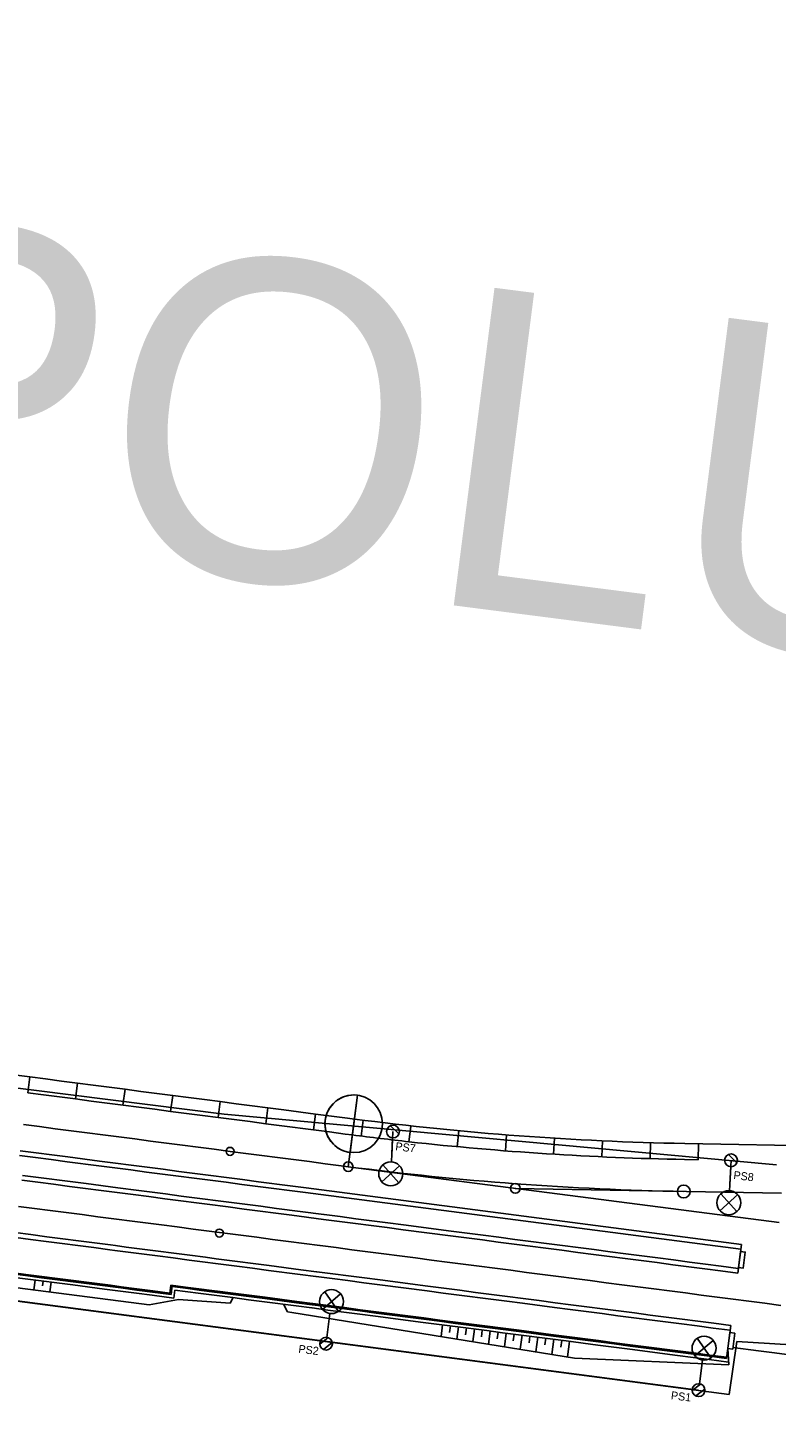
# Model space of a CAD drawing. Extents: x -669661 to -669105, y -977202 to -977030.
# Drawn here: x -669175.034 to -669172.695, y -977098.424 to -977094.133 of the extents above; entities that cross this region are included whole.
import ezdxf

# ---------------------------------------------------------------- set-up
doc = ezdxf.new("R2010")
doc.units = 0
doc.layers.add('Schéma', color=7, linetype='Continuous')

msp = doc.modelspace()

# ---------------------------------------------------------------- linework, layer by layer
at = {"layer": 'Schéma'}
for p, q in [((-669174.42, -977097.5262), (-669175.313, -977097.4136)), ((-669174.0323, -977097.6905), (-669174.0034, -977097.4674)), ((-669172.6955, -977097.6847), (-669174.42, -977097.5262)), ((-669175.0459, -977097.5589), (-669174.9963, -977097.5653)), ((-669174.9963, -977097.5653), (-669174.9468, -977097.5718)), ((-669174.9468, -977097.5718), (-669174.8972, -977097.5782)), ((-669174.8972, -977097.5782), (-669174.8476, -977097.5846)), ((-669174.8476, -977097.5846), (-669174.798, -977097.5911)), ((-669173.9008, -977097.5627), (-669173.8751, -977097.587)), ((-669173.8927, -977097.5807), (-669173.8966, -977097.6556)), ((-669173.6872, -977097.5783), (-669173.6919, -977097.628)), ((-669174.798, -977097.5911), (-669174.7484, -977097.5975)), ((-669174.7484, -977097.5975), (-669174.6988, -977097.6039)), ((-669174.6988, -977097.6039), (-669174.6493, -977097.6104)), ((-669174.6493, -977097.6104), (-669174.5997, -977097.6168)), ((-669174.5997, -977097.6168), (-669174.5501, -977097.6233)), ((-669174.5501, -977097.6233), (-669174.5005, -977097.6297)), ((-669174.5005, -977097.6297), (-669174.4509, -977097.6361)), ((-669173.8937, -977097.6006), (-669173.8976, -977097.6755)), ((-669173.5377, -977097.5911), (-669173.5416, -977097.641)), ((-669173.3881, -977097.6016), (-669173.3912, -977097.6515)), ((-669173.2383, -977097.6097), (-669173.2406, -977097.6597)), ((-669173.0884, -977097.6154), (-669173.0899, -977097.6654)), ((-669172.9385, -977097.6188), (-669172.9394, -977097.6688)), ((-669174.4509, -977097.6361), (-669174.4013, -977097.6426)), ((-669174.4013, -977097.6426), (-669174.3518, -977097.649)), ((-669174.3518, -977097.649), (-669174.3022, -977097.6555)), ((-669174.3022, -977097.6555), (-669174.2526, -977097.6619)), ((-669174.2526, -977097.6619), (-669174.203, -977097.6683)), ((-669174.203, -977097.6683), (-669174.1534, -977097.6748)), ((-669172.8452, -977097.6526), (-669172.8195, -977097.6769)), ((-669172.8371, -977097.6706), (-669172.8409, -977097.7455)), ((-669174.1534, -977097.6748), (-669174.1038, -977097.6812)), ((-669174.1038, -977097.6812), (-669174.0543, -977097.6876)), ((-669174.0543, -977097.6876), (-669174.0323, -977097.6905)), ((-669174.0323, -977097.6905), (-669172.6867, -977097.8652)), ((-669173.8717, -977097.6879), (-669173.9274, -977097.7381)), ((-669173.9246, -977097.6852), (-669173.8744, -977097.7408)), ((-669172.8381, -977097.6906), (-669172.842, -977097.7655)), ((-669173.9014, -977097.7505), (-669173.9014, -977097.7505)), ((-669173.5106, -977097.7582), (-669172.6799, -977097.7736)), ((-669172.8161, -977097.7778), (-669172.8717, -977097.828)), ((-669172.869, -977097.7751), (-669172.8188, -977097.8308)), ((-669175.0619, -977097.8145), (-669175.0123, -977097.8209)), ((-669175.0123, -977097.8209), (-669174.9627, -977097.8273)), ((-669174.9627, -977097.8273), (-669174.9131, -977097.8338)), ((-669174.9131, -977097.8338), (-669174.8635, -977097.8402)), ((-669174.8635, -977097.8402), (-669174.814, -977097.8466)), ((-669172.8458, -977097.8404), (-669172.8458, -977097.8404)), ((-669174.814, -977097.8466), (-669174.7644, -977097.8531)), ((-669174.7644, -977097.8531), (-669174.7479, -977097.8552)), ((-669174.7479, -977097.8552), (-669174.7148, -977097.8595)), ((-669174.7148, -977097.8595), (-669174.6652, -977097.866)), ((-669174.6652, -977097.866), (-669174.6156, -977097.8724)), ((-669174.6156, -977097.8724), (-669174.566, -977097.8788)), ((-669174.566, -977097.8788), (-669174.5165, -977097.8853)), ((-669174.5165, -977097.8853), (-669174.4669, -977097.8917)), ((-669176.5596, -977097.9156), (-669172.9388, -977098.388)), ((-669172.9388, -977098.388), (-669176.5333, -977097.9176)), ((-669172.9388, -977098.388), (-669176.5333, -977097.9176)), ((-669172.8431, -977098.4024), (-669176.5328, -977097.9177)), ((-669174.4669, -977097.8917), (-669174.4342, -977097.896)), ((-669174.4342, -977097.896), (-669174.4173, -977097.8982)), ((-669174.4173, -977097.8982), (-669174.3677, -977097.9046)), ((-669174.3677, -977097.9046), (-669174.3181, -977097.911)), ((-669174.3181, -977097.911), (-669174.2685, -977097.9175)), ((-669174.2685, -977097.9175), (-669174.2189, -977097.9239)), ((-669174.2189, -977097.9239), (-669174.1694, -977097.9303)), ((-669174.1694, -977097.9303), (-669174.1206, -977097.9367)), ((-669174.1206, -977097.9367), (-669174.1198, -977097.9368)), ((-669174.1198, -977097.9368), (-669174.0702, -977097.9432)), ((-669174.0702, -977097.9432), (-669174.0206, -977097.9497)), ((-669174.0206, -977097.9497), (-669173.971, -977097.9561)), ((-669173.971, -977097.9561), (-669173.9214, -977097.9625)), ((-669173.9214, -977097.9625), (-669173.8719, -977097.969)), ((-669173.8719, -977097.969), (-669173.8223, -977097.9754)), ((-669172.8045, -977097.9331), (-669172.8162, -977098.0229)), ((-669175.5178, -977098.01), (-669174.6539, -977098.1217)), ((-669173.8223, -977097.9754), (-669173.7727, -977097.9819)), ((-669173.7727, -977097.9819), (-669173.7231, -977097.9883)), ((-669173.7231, -977097.9883), (-669173.6735, -977097.9947)), ((-669173.6735, -977097.9947), (-669173.6239, -977098.0012)), ((-669173.6239, -977098.0012), (-669173.5744, -977098.0076)), ((-669173.5744, -977098.0076), (-669173.5248, -977098.014)), ((-669173.5248, -977098.014), (-669173.4752, -977098.0205)), ((-669175.0136, -977098.0752), (-669175.0096, -977098.0446)), ((-669174.9867, -977098.0624), (-669174.9848, -977098.0478)), ((-669174.964, -977098.0816), (-669174.96, -977098.051)), ((-669174.5857, -977098.0603), (-669174.589, -977098.0851)), ((-669173.4752, -977098.0205), (-669173.4256, -977098.0269)), ((-669173.4256, -977098.0269), (-669173.376, -977098.0334)), ((-669173.376, -977098.0334), (-669173.3264, -977098.0398)), ((-669173.3264, -977098.0398), (-669173.2769, -977098.0462)), ((-669173.2769, -977098.0462), (-669173.2273, -977098.0527)), ((-669173.2273, -977098.0527), (-669173.1777, -977098.0591)), ((-669173.1777, -977098.0591), (-669173.1281, -977098.0655)), ((-669174.5818, -977098.0608), (-669174.5855, -977098.0896)), ((-669174.5737, -977098.076), (-669174.5769, -977098.1008)), ((-669174.1128, -977098.1362), (-669174.056, -977098.0875)), ((-669174.1056, -977098.0811), (-669174.0631, -977098.1427)), ((-669173.1281, -977098.0655), (-669173.0785, -977098.072)), ((-669173.0785, -977098.072), (-669173.0289, -977098.0784)), ((-669173.0289, -977098.0784), (-669172.9794, -977098.0849)), ((-669172.9794, -977098.0849), (-669172.9298, -977098.0913)), ((-669172.9298, -977098.0913), (-669172.8802, -977098.0977)), ((-669172.8802, -977098.0977), (-669172.8306, -977098.1042)), ((-669174.6539, -977098.1217), (-669174.5623, -977098.1056)), ((-669172.8306, -977098.1042), (-669172.781, -977098.1106)), ((-669172.781, -977098.1106), (-669172.7314, -977098.1171)), ((-669172.7314, -977098.1171), (-669172.6819, -977098.1235)), ((-669174.0892, -977098.149), (-669174.0989, -977098.2234)), ((-669173.7377, -977098.1846), (-669173.7424, -977098.2207)), ((-669173.7129, -977098.1878), (-669173.7156, -977098.2086)), ((-669172.8374, -977098.1865), (-669172.8508, -977098.2896)), ((-669174.1212, -977098.2447), (-669174.095, -977098.2244)), ((-669173.6881, -977098.191), (-669173.693, -977098.2287)), ((-669173.6633, -977098.1942), (-669173.666, -977098.2151)), ((-669173.6385, -977098.1974), (-669173.6436, -977098.2367)), ((-669173.6137, -977098.2006), (-669173.6164, -977098.2215)), ((-669173.5889, -977098.2039), (-669173.5942, -977098.2446)), ((-669173.5641, -977098.2071), (-669173.5668, -977098.228)), ((-669173.5393, -977098.2103), (-669173.5448, -977098.2526)), ((-669173.5145, -977098.2135), (-669173.5172, -977098.2344)), ((-669173.4897, -977098.2167), (-669173.4954, -977098.2606)), ((-669173.4649, -977098.22), (-669173.4677, -977098.2408)), ((-669173.4402, -977098.2232), (-669173.446, -977098.2685)), ((-669173.4154, -977098.2264), (-669173.4181, -977098.2473)), ((-669173.3906, -977098.2296), (-669173.3967, -977098.2765)), ((-669172.9426, -977098.2263), (-669172.9001, -977098.2879)), ((-669174.1099, -977098.2611), (-669174.0819, -977098.2395)), ((-669173.3658, -977098.2328), (-669173.3685, -977098.2537)), ((-669173.341, -977098.2361), (-669173.3473, -977098.2845)), ((-669172.9497, -977098.2815), (-669172.8929, -977098.2328)), ((-669172.8468, -977098.2584), (-669172.844, -977098.3092)), ((-669172.8186, -977098.2366), (-669172.8431, -977098.4024)), ((-669172.4538, -977098.259), (-669172.8186, -977098.2366)), ((-669172.9261, -977098.2942), (-669172.9358, -977098.3686)), ((-669172.9582, -977098.3899), (-669172.9319, -977098.3697)), ((-669172.9468, -977098.4063), (-669172.9188, -977098.3848))]:
    msp.add_line(p, q, dxfattribs=at)
for points in [[(-669175.0762, -977097.4037), (-669175.0266, -977097.4101), (-669174.977, -977097.4166), (-669174.9274, -977097.423), (-669174.8779, -977097.4294), (-669174.8283, -977097.4359), (-669174.7291, -977097.4488), (-669174.6795, -977097.4552), (-669174.6299, -977097.4616), (-669174.5804, -977097.4681), (-669174.5308, -977097.4745), (-669174.4812, -977097.481), (-669174.4316, -977097.4874), (-669174.382, -977097.4938), (-669174.3324, -977097.5003), (-669174.2829, -977097.5067), (-669174.2333, -977097.5131), (-669174.1341, -977097.526), (-669174.0845, -977097.5325), (-669174.0349, -977097.5389), (-669174.013, -977097.5417)], [(-669175.0331, -977097.4597), (-669175.0266, -977097.4101)], [(-669175.0331, -977097.4597), (-669174.9835, -977097.4662), (-669174.9339, -977097.4726), (-669174.8843, -977097.479), (-669174.8347, -977097.4855), (-669174.7355, -977097.4983), (-669174.686, -977097.5048), (-669174.6364, -977097.5112), (-669174.5868, -977097.5177), (-669174.5372, -977097.5241), (-669174.4876, -977097.5305), (-669174.438, -977097.537), (-669174.3885, -977097.5434), (-669174.3389, -977097.5498), (-669174.2893, -977097.5563), (-669174.2397, -977097.5627), (-669174.1405, -977097.5756), (-669174.091, -977097.582), (-669174.0414, -977097.5885), (-669174.0195, -977097.5913)], [(-669174.8843, -977097.479), (-669174.8779, -977097.4294)], [(-669174.7356, -977097.4983), (-669174.7291, -977097.4488)], [(-669174.5868, -977097.5177), (-669174.5804, -977097.4681)], [(-669174.4381, -977097.537), (-669174.4316, -977097.4874)], [(-669174.0034, -977097.4674), (-669174.0265, -977097.6459), (-669174.0265, -977097.6459)], [(-669174.2893, -977097.5563), (-669174.2829, -977097.5067)], [(-669174.1405, -977097.5756), (-669174.1341, -977097.526)], [(-669173.9918, -977097.5949), (-669173.9854, -977097.5453)], [(-669173.8428, -977097.6126), (-669173.8366, -977097.5646)], [(-669172.9817, -977097.618), (-669172.533, -977097.6263)], [(-669175.0585, -977097.6556), (-669175.0089, -977097.662), (-669174.9593, -977097.6684), (-669174.9097, -977097.6749), (-669174.8106, -977097.6878), (-669174.761, -977097.6942), (-669174.7114, -977097.7006), (-669174.6618, -977097.7071), (-669174.6122, -977097.7135), (-669174.5626, -977097.72), (-669174.5131, -977097.7264), (-669174.4635, -977097.7328), (-669174.4139, -977097.7393), (-669174.3643, -977097.7457), (-669174.3147, -977097.7521), (-669174.166, -977097.7715), (-669172.8065, -977097.948)], [(-669175.0566, -977097.6407), (-669175.007, -977097.6471), (-669174.9574, -977097.6536), (-669174.9078, -977097.66), (-669174.8086, -977097.6729), (-669174.759, -977097.6793), (-669174.7095, -977097.6858), (-669174.6599, -977097.6922), (-669174.6103, -977097.6986), (-669174.5607, -977097.7051), (-669174.5111, -977097.7115), (-669174.4615, -977097.718), (-669174.412, -977097.7244), (-669174.3624, -977097.7308), (-669174.3128, -977097.7373), (-669174.2136, -977097.7501), (-669174.164, -977097.7566), (-669172.8045, -977097.9331)], [(-669172.9827, -977097.668), (-669172.9394, -977097.6688)], [(-669175.0513, -977097.7326), (-669175.0017, -977097.7391), (-669174.9521, -977097.7455), (-669174.9025, -977097.752), (-669174.8529, -977097.7584), (-669174.8033, -977097.7648), (-669174.7537, -977097.7713), (-669174.7373, -977097.7734), (-669174.7042, -977097.7777), (-669174.6546, -977097.7841), (-669174.605, -977097.7906), (-669174.5554, -977097.797), (-669174.5058, -977097.8035), (-669174.4562, -977097.8099), (-669174.4236, -977097.8141), (-669174.4067, -977097.8163), (-669174.3571, -977097.8228), (-669174.3075, -977097.8292), (-669174.2579, -977097.8357), (-669174.2083, -977097.8421), (-669174.1099, -977097.8549), (-669174.1092, -977097.855), (-669174.0596, -977097.8614), (-669174.01, -977097.8678), (-669173.9604, -977097.8743), (-669173.9108, -977097.8807), (-669173.8612, -977097.8872), (-669173.7125, -977097.9065), (-669173.6629, -977097.9129), (-669173.6133, -977097.9194), (-669173.5637, -977097.9258), (-669173.5142, -977097.9322), (-669173.4646, -977097.9387), (-669173.415, -977097.9451), (-669173.3654, -977097.9515), (-669173.3158, -977097.958), (-669173.2662, -977097.9644), (-669173.2167, -977097.9709), (-669173.1671, -977097.9773), (-669173.1175, -977097.9837), (-669173.0679, -977097.9902), (-669173.0183, -977097.9966), (-669172.9687, -977098.0031), (-669172.9191, -977098.0095), (-669172.8696, -977098.0159), (-669172.8162, -977098.0229)], [(-669175.0493, -977097.7178), (-669174.9997, -977097.7242), (-669174.9006, -977097.7371), (-669174.851, -977097.7435), (-669174.7518, -977097.7564), (-669174.7354, -977097.7585), (-669174.7022, -977097.7628), (-669174.6526, -977097.7693), (-669174.6031, -977097.7757), (-669174.5535, -977097.7822), (-669174.5039, -977097.7886), (-669174.4217, -977097.7993), (-669174.4047, -977097.8015), (-669174.3551, -977097.8079), (-669174.3056, -977097.8143), (-669174.256, -977097.8208), (-669174.108, -977097.84), (-669174.1072, -977097.8401), (-669174.0576, -977097.8465), (-669174.0081, -977097.853), (-669173.9585, -977097.8594), (-669173.9089, -977097.8658), (-669173.8593, -977097.8723), (-669173.7106, -977097.8916), (-669173.661, -977097.898), (-669173.6114, -977097.9045), (-669173.5618, -977097.9109), (-669173.5122, -977097.9174), (-669173.4626, -977097.9238), (-669173.4131, -977097.9302), (-669173.3635, -977097.9367), (-669173.3139, -977097.9431), (-669173.2643, -977097.9495), (-669173.2147, -977097.956), (-669173.1651, -977097.9624), (-669173.1156, -977097.9689), (-669173.066, -977097.9753), (-669173.0164, -977097.9817), (-669172.9668, -977097.9882), (-669172.9172, -977097.9946), (-669172.8676, -977098.0011), (-669172.8143, -977098.008)], [(-669175.124, -977097.9047), (-669175.0248, -977097.9176), (-669174.9753, -977097.924), (-669174.9257, -977097.9305), (-669174.8761, -977097.9369), (-669174.8265, -977097.9433), (-669174.7769, -977097.9498), (-669174.7605, -977097.9519), (-669174.7273, -977097.9562), (-669174.6778, -977097.9627), (-669174.6282, -977097.9691), (-669174.5786, -977097.9755), (-669174.529, -977097.982), (-669174.4794, -977097.9884), (-669174.4468, -977097.9926), (-669174.4298, -977097.9948), (-669174.3803, -977098.0013), (-669174.3307, -977098.0077), (-669174.2811, -977098.0142), (-669174.1819, -977098.027), (-669174.1331, -977098.0334), (-669174.1323, -977098.0335), (-669174.0828, -977098.0399), (-669174.0332, -977098.0463), (-669173.9836, -977098.0528), (-669173.934, -977098.0592), (-669173.7853, -977098.0785), (-669173.7357, -977098.085), (-669173.6861, -977098.0914), (-669173.5869, -977098.1043), (-669173.5373, -977098.1107), (-669173.4877, -977098.1172), (-669173.3886, -977098.13), (-669173.339, -977098.1365), (-669173.2398, -977098.1494), (-669173.1902, -977098.1558), (-669173.1407, -977098.1622), (-669173.0911, -977098.1687), (-669172.9919, -977098.1816), (-669172.9423, -977098.188), (-669172.8927, -977098.1944), (-669172.8394, -977098.2014)], [(-669175.0725, -977097.8963), (-669175.0229, -977097.9027), (-669174.9733, -977097.9091), (-669174.9237, -977097.9156), (-669174.8742, -977097.922), (-669174.8246, -977097.9285), (-669174.775, -977097.9349), (-669174.7585, -977097.937), (-669174.7254, -977097.9413), (-669174.6758, -977097.9478), (-669174.6262, -977097.9542), (-669174.5767, -977097.9607), (-669174.5271, -977097.9671), (-669174.4775, -977097.9735), (-669174.4449, -977097.9778), (-669174.4279, -977097.98), (-669174.3783, -977097.9864), (-669174.3287, -977097.9928), (-669174.2792, -977097.9993), (-669174.18, -977098.0122), (-669174.1312, -977098.0185), (-669174.1304, -977098.0186), (-669174.0808, -977098.025), (-669174.0312, -977098.0315), (-669173.9817, -977098.0379), (-669173.9321, -977098.0443), (-669173.7833, -977098.0637), (-669173.7337, -977098.0701), (-669173.6842, -977098.0765), (-669173.6346, -977098.083), (-669173.585, -977098.0894), (-669173.5354, -977098.0959), (-669173.4858, -977098.1023), (-669173.4362, -977098.1087), (-669173.3866, -977098.1152), (-669173.3371, -977098.1216), (-669173.2875, -977098.128), (-669173.2379, -977098.1345), (-669173.1883, -977098.1409), (-669173.1387, -977098.1474), (-669173.0891, -977098.1538), (-669173.0396, -977098.1602), (-669172.99, -977098.1667), (-669172.9404, -977098.1731), (-669172.8908, -977098.1796), (-669172.8374, -977098.1865)], [(-669175.5641, -977097.9585), (-669175.4853, -977097.9687), (-669175.4357, -977097.9752), (-669175.3861, -977097.9816), (-669175.3365, -977097.988), (-669175.2869, -977097.9945), (-669175.2373, -977098.0009), (-669175.1878, -977098.0074), (-669175.1382, -977098.0138), (-669175.039, -977098.0267), (-669174.9894, -977098.0331), (-669174.9398, -977098.0395), (-669174.8903, -977098.046), (-669174.8407, -977098.0524), (-669174.7911, -977098.0589), (-669174.7746, -977098.061), (-669174.7415, -977098.0653), (-669174.6919, -977098.0717), (-669174.6423, -977098.0782), (-669174.589, -977098.0851)], [(-669175.5605, -977097.963), (-669175.5354, -977097.9663), (-669175.4858, -977097.9727), (-669175.4362, -977097.9791), (-669175.3866, -977097.9856), (-669175.337, -977097.992), (-669175.2874, -977097.9984), (-669175.2379, -977098.0049), (-669175.1883, -977098.0113), (-669175.1387, -977098.0178), (-669175.0395, -977098.0306), (-669174.9899, -977098.0371), (-669174.9404, -977098.0435), (-669174.8908, -977098.0499), (-669174.7916, -977098.0628), (-669174.7751, -977098.065), (-669174.742, -977098.0693), (-669174.6924, -977098.0757), (-669174.6429, -977098.0821), (-669174.5855, -977098.0896)], [(-669175.5458, -977097.975), (-669175.4871, -977097.9826), (-669175.4375, -977097.989), (-669175.3879, -977097.9955), (-669175.3383, -977098.0019), (-669175.2887, -977098.0084), (-669175.2391, -977098.0148), (-669175.1896, -977098.0212), (-669175.14, -977098.0277), (-669175.0408, -977098.0406), (-669174.9912, -977098.047), (-669174.9416, -977098.0534), (-669174.8921, -977098.0599), (-669174.7929, -977098.0727), (-669174.7764, -977098.0749), (-669174.7433, -977098.0792), (-669174.6937, -977098.0856), (-669174.6441, -977098.0921), (-669174.5769, -977098.1008)], [(-669174.5857, -977098.0603), (-669174.54, -977098.0663), (-669174.4904, -977098.0727), (-669174.4577, -977098.0769), (-669174.4408, -977098.0791), (-669174.3912, -977098.0856), (-669174.3416, -977098.092), (-669174.292, -977098.0984), (-669174.1929, -977098.1113), (-669174.1441, -977098.1177), (-669174.1433, -977098.1178), (-669174.0937, -977098.1242), (-669174.0441, -977098.1306), (-669173.9945, -977098.1371), (-669173.9449, -977098.1435), (-669173.7962, -977098.1628), (-669173.7466, -977098.1693), (-669173.697, -977098.1757), (-669173.5979, -977098.1886), (-669173.5483, -977098.195), (-669173.4987, -977098.2015), (-669173.3995, -977098.2143), (-669173.3499, -977098.2208), (-669173.2508, -977098.2337), (-669173.2012, -977098.2401), (-669173.1516, -977098.2465), (-669173.102, -977098.253), (-669173.0029, -977098.2658), (-669172.9533, -977098.2723), (-669172.9037, -977098.2787), (-669172.8503, -977098.2857)], [(-669174.5823, -977098.0648), (-669174.5405, -977098.0702), (-669174.4909, -977098.0767), (-669174.4583, -977098.0809), (-669174.4413, -977098.0831), (-669174.3917, -977098.0895), (-669174.3421, -977098.096), (-669174.2925, -977098.1024), (-669174.1934, -977098.1153), (-669174.1446, -977098.1216), (-669174.1438, -977098.1217), (-669174.0942, -977098.1282), (-669173.995, -977098.141), (-669173.9455, -977098.1475), (-669173.7967, -977098.1668), (-669173.7471, -977098.1732), (-669173.6975, -977098.1797), (-669173.5984, -977098.1926), (-669173.5488, -977098.199), (-669173.4992, -977098.2054), (-669173.4, -977098.2183), (-669173.3505, -977098.2247), (-669173.2513, -977098.2376), (-669173.2017, -977098.2441), (-669173.1521, -977098.2505), (-669173.0034, -977098.2698), (-669172.9538, -977098.2762), (-669172.9042, -977098.2827), (-669172.8508, -977098.2896)], [(-669174.5737, -977098.076), (-669174.5418, -977098.0801), (-669174.4922, -977098.0866), (-669174.4595, -977098.0908), (-669174.4426, -977098.093), (-669174.393, -977098.0995), (-669174.3434, -977098.1059), (-669174.2938, -977098.1123), (-669174.1947, -977098.1252), (-669174.1459, -977098.1315), (-669174.1451, -977098.1316), (-669174.0955, -977098.1381), (-669173.9963, -977098.151), (-669173.9467, -977098.1574), (-669173.798, -977098.1767), (-669173.7484, -977098.1832), (-669173.6988, -977098.1896), (-669173.5997, -977098.2025), (-669173.5501, -977098.2089), (-669173.5005, -977098.2153), (-669173.4013, -977098.2282), (-669173.3517, -977098.2347), (-669173.2526, -977098.2475), (-669173.203, -977098.254), (-669173.1534, -977098.2604), (-669173.0047, -977098.2797), (-669172.9551, -977098.2862), (-669172.9055, -977098.2926), (-669172.8445, -977098.3005)], [(-669174.5623, -977098.1056), (-669174.4011, -977098.1163), (-669174.392, -977098.0992)], [(-669174.2079, -977098.1457), (-669174.2216, -977098.1436), (-669174.2341, -977098.1201)], [(-669174.2079, -977098.1457), (-669173.3255, -977098.288), (-669172.844, -977098.3092)], [(-669172.8313, -977098.2554), (-669172.7508, -977098.2658), (-669172.7012, -977098.2722), (-669172.6633, -977098.2772)]]:
    msp.add_lwpolyline(points, dxfattribs=at)
for points in [[(-669172.8074, -977097.9554), (-669172.7926, -977097.9573), (-669172.799, -977098.0069), (-669172.8139, -977098.005)], [(-669172.8403, -977098.2088), (-669172.8255, -977098.2107), (-669172.8319, -977098.2603), (-669172.8468, -977098.2584)]]:
    msp.add_lwpolyline(points, close=True, dxfattribs=at)
for centre, radius in [((-669174.015, -977097.5566), 0.09), ((-669173.8927, -977097.5807), 0.02), ((-669174.4013, -977097.6426), 0.0125), ((-669172.8371, -977097.6706), 0.02), ((-669174.0323, -977097.6905), 0.015), ((-669173.8995, -977097.713), 0.0375), ((-669173.5106, -977097.7582), 0.015), ((-669172.9845, -977097.768), 0.02), ((-669172.8439, -977097.8029), 0.0375), ((-669174.4345, -977097.8979), 0.0125), ((-669174.0844, -977098.1119), 0.0374), ((-669174.1014, -977098.2432), 0.02), ((-669172.9213, -977098.2571), 0.0374), ((-669172.9384, -977098.3884), 0.02)]:
    msp.add_circle(centre, radius, dxfattribs=at)
for centre, radius, start, end in [((-669174.015, -977097.5566), 0.09, 82.602, 262.6005), ((-669172.8091, -977088.2696), 9.35, 262.60197, 268.942), ((-669172.8091, -977088.2696), 9.4, 262.60197, 263.68635), ((-669172.8091, -977088.2696), 9.4, 263.68635, 268.942), ((-669172.8091, -977088.2696), 9.5, 262.60197, 268.942)]:
    msp.add_arc(centre, radius, start, end, dxfattribs=at)

# ---------------------------------------------------------------- texts
for s, height, rotation, p in [('DOLNÍ POLUBNÝ', 1, 352.6919, (-669180.15, -977095.1109)), ('PS7', 0.025, 353.1527, (-669173.8861, -977097.6388)), ('PS8', 0.025, 353.1527, (-669172.8305, -977097.7287)), ('PS2', 0.025, 353.1527, (-669174.1888, -977098.2713)), ('PS1', 0.025, 353.1527, (-669173.0258, -977098.4165))]:
    msp.add_text(s, height=height, rotation=rotation, dxfattribs=at).set_placement(p)

doc.saveas('drawing.dxf')
